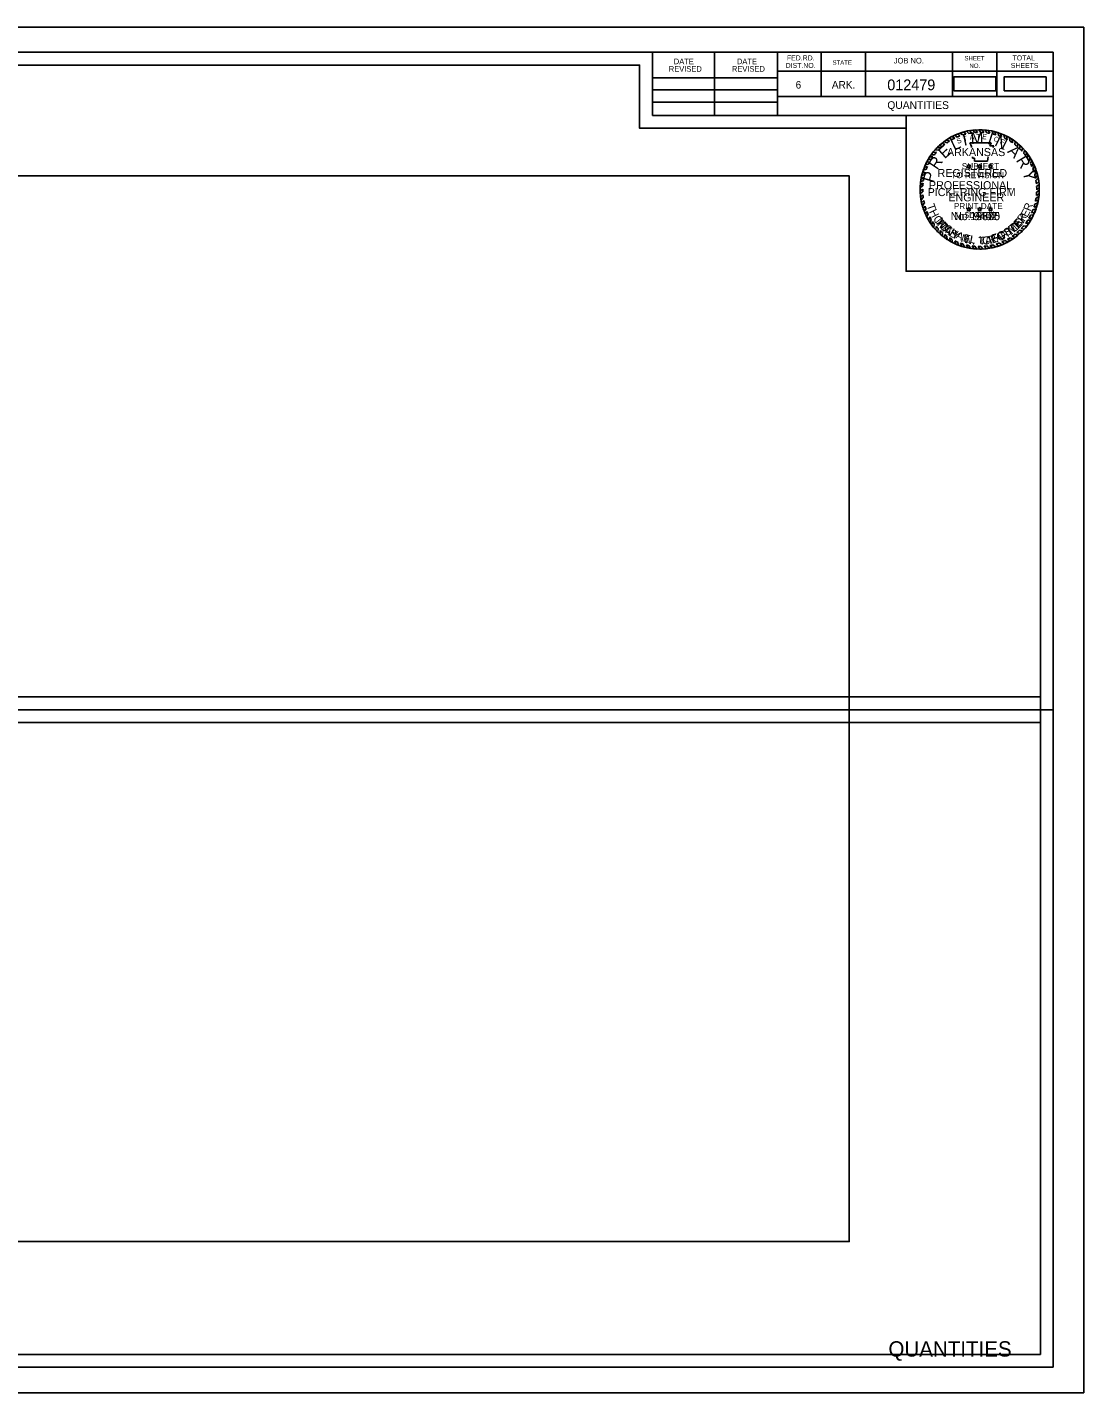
# Model space of a CAD drawing. Extents: x 1369290 to 1371547, y 379683 to 379897.
# Drawn here: x 1370188.9 to 1370354, y 379683.5 to 379896.8 of the extents above; entities that cross this region are included whole.
import ezdxf

# ---------------------------------------------------------------- set-up
doc = ezdxf.new("R2010")
doc.units = 0
for name, color, linetype in [('Default', 7, 'Continuous'), ('R_Border', 7, 'Continuous'), ('R_Border Notes', 7, 'Continuous'), ('R_Border Plan-Plan', 7, 'Continuous'), ('R_Border Title', 7, 'Continuous'), ('R_No Plot', 7, 'Continuous'), ('STAMP_PE_CRAFTON', 7, 'Continuous'), ('STAMP_PE_FOSTER', 7, 'Continuous'), ('STAMP_PE_SEAL-INFO', 7, 'Continuous'), ('STAMP_PE_TAEGTMEYER', 7, 'Continuous'), ('STAMP_PE_TXT', 7, 'Continuous'), ('STAMP_PRELIMINARY', 7, 'Continuous')]:
    doc.layers.add(name, color=color, linetype=linetype)

msp = doc.modelspace()

# ---------------------------------------------------------------- linework, layer by layer
at = {"layer": 'Default'}
for points in [[(1370333.72, 379886.89), (1370340.28, 379886.89), (1370340.28, 379889.08), (1370333.72, 379889.08)], [(1370341.59, 379886.89), (1370348.15, 379886.89), (1370348.15, 379889.08), (1370341.59, 379889.08)], [(1370057.32, 379707.1), (1370317.39, 379707.1), (1370317.39, 379873.59), (1370057.32, 379873.59)]]:
    msp.add_lwpolyline(points, close=True, dxfattribs=at)
at = {"layer": 'R_Border'}
for p, q in [((1370033.09, 379892.93), (1370349.27, 379892.93)), ((1370286.63, 379883.05), (1370286.63, 379892.93)), ((1370296.31, 379883.05), (1370296.31, 379892.93)), ((1370306.17, 379892.93), (1370306.17, 379883.05)), ((1370313.01, 379892.93), (1370313.01, 379885.99)), ((1370319.95, 379892.93), (1370319.95, 379885.99)), ((1370333.53, 379892.93), (1370333.53, 379885.99)), ((1370340.47, 379892.93), (1370340.47, 379885.99)), ((1370349.27, 379687.47), (1370349.27, 379892.93)), ((1370286.63, 379888.91), (1370306.17, 379888.91)), ((1370349.27, 379889.99), (1370306.17, 379889.99)), ((1370349.27, 379890.01), (1370349.27, 379890.01)), ((1370286.63, 379887.05), (1370306.17, 379887.05)), ((1370286.63, 379885.11), (1370306.17, 379885.11)), ((1370349.27, 379885.99), (1370306.17, 379885.99)), ((1370309.13, 379885.99), (1370349.27, 379885.99)), ((1370349.27, 379883.05), (1370286.63, 379883.05)), ((1370349.27, 379687.47), (1370033.09, 379687.47))]:
    msp.add_line(p, q, dxfattribs=at)
at = {"layer": 'R_Border Plan-Plan'}
msp.add_line((1370033.09, 379790.2), (1370349.27, 379790.2), dxfattribs=at)
at = {"layer": 'R_No Plot'}
for points in [[(1370020.68, 379896.82), (1370354.02, 379896.82), (1370354.02, 379683.48), (1370020.68, 379683.48)], [(1370347.27, 379792.2), (1370035.09, 379792.2), (1370035.09, 379890.93), (1370284.63, 379890.93), (1370284.63, 379881.05), (1370302.17, 379881.05), (1370326.27, 379881.05), (1370326.27, 379858.71), (1370347.27, 379858.71)], [(1370035.09, 379890.93), (1370284.63, 379890.93), (1370284.63, 379881.05), (1370302.17, 379881.05), (1370326.27, 379881.05), (1370326.27, 379858.71), (1370347.27, 379858.71), (1370347.27, 379689.47), (1370035.09, 379689.47)], [(1370326.27, 379883.05), (1370349.27, 379883.05), (1370349.27, 379858.71), (1370326.27, 379858.71)], [(1370035.09, 379788.2), (1370347.27, 379788.2), (1370347.27, 379689.47), (1370035.09, 379689.47)]]:
    msp.add_lwpolyline(points, close=True, dxfattribs=at)
at = {"layer": 'STAMP_PE_SEAL-INFO'}
for p, q in [((1370333.44, 379879.75), (1370333.91, 379879.52)), ((1370333.88, 379879.96), (1370334.26, 379879.68)), ((1370334.38, 379880.18), (1370334.68, 379879.85)), ((1370334.73, 379880.3), (1370335.11, 379880)), ((1370335.32, 379880.49), (1370335.61, 379880.14)), ((1370335.71, 379880.58), (1370336.07, 379880.24)), ((1370336.19, 379880.68), (1370336.49, 379880.31)), ((1370336.71, 379880.75), (1370336.99, 379880.37)), ((1370337.44, 379880.4), (1370337.13, 379880.79)), ((1370337.94, 379880.4), (1370337.66, 379880.81)), ((1370338.4, 379880.38), (1370338.14, 379880.81)), ((1370338.9, 379880.33), (1370338.61, 379880.77)), ((1370339.33, 379880.27), (1370339.07, 379880.72)), ((1370339.89, 379880.15), (1370339.72, 379880.61)), ((1370340.29, 379880.04), (1370340.13, 379880.51)), ((1370340.75, 379879.89), (1370340.6, 379880.37)), ((1370341.16, 379879.73), (1370341.02, 379880.23)), ((1370341.63, 379879.53), (1370341.52, 379880.02)), ((1370342.07, 379879.3), (1370341.98, 379879.81)), ((1370330.81, 379877.69), (1370331.33, 379877.65)), ((1370331.13, 379878.04), (1370331.68, 379877.99)), ((1370331.47, 379878.36), (1370331.93, 379878.22)), ((1370331.81, 379878.66), (1370332.34, 379878.56)), ((1370332.19, 379878.99), (1370332.64, 379878.78)), ((1370332.61, 379879.25), (1370333.05, 379879.05)), ((1370333, 379879.5), (1370333.43, 379879.27)), ((1370336.24, 379878.78), (1370339.59, 379878.78)), ((1370336.37, 379878.47), (1370336.24, 379878.78)), ((1370336.47, 379878.18), (1370336.37, 379878.47)), ((1370336.48, 379878.06), (1370336.47, 379878.18)), ((1370339.59, 379878.78), (1370339.36, 379878.29)), ((1370339.36, 379878.29), (1370340, 379878.29)), ((1370340, 379878.29), (1370339.85, 379878.06)), ((1370342.46, 379879.07), (1370342.42, 379879.57)), ((1370342.89, 379878.78), (1370342.86, 379879.3)), ((1370343.25, 379878.52), (1370343.29, 379879)), ((1370343.7, 379878.15), (1370343.72, 379878.67)), ((1370344.01, 379877.85), (1370344.08, 379878.35)), ((1370344.37, 379877.48), (1370344.44, 379878.01)), ((1370344.65, 379877.16), (1370344.78, 379877.63)), ((1370329.29, 379875.35), (1370329.79, 379875.46)), ((1370329.47, 379875.74), (1370329.97, 379875.81)), ((1370329.71, 379876.17), (1370330.19, 379876.19)), ((1370329.95, 379876.57), (1370330.47, 379876.6)), ((1370330.19, 379876.91), (1370330.69, 379876.91)), ((1370330.46, 379877.28), (1370331.01, 379877.3)), ((1370336.67, 379876.35), (1370336.64, 379876.57)), ((1370336.98, 379876.35), (1370336.67, 379876.35)), ((1370336.98, 379875.92), (1370336.98, 379876.35)), ((1370339.01, 379875.92), (1370336.98, 379875.92)), ((1370339.03, 379876.26), (1370339.01, 379875.92)), ((1370339.11, 379876.57), (1370339.03, 379876.26)), ((1370344.97, 379876.75), (1370345.1, 379877.25)), ((1370345.19, 379876.43), (1370345.37, 379876.89)), ((1370345.5, 379875.93), (1370345.68, 379876.42)), ((1370345.7, 379875.57), (1370345.92, 379876.01)), ((1370345.93, 379875.08), (1370346.15, 379875.57)), ((1370329.06, 379873.36), (1370328.59, 379873.11)), ((1370328.69, 379873.6), (1370329.16, 379873.8)), ((1370328.8, 379874.01), (1370329.27, 379874.18)), ((1370328.95, 379874.51), (1370329.44, 379874.65)), ((1370329.1, 379874.92), (1370329.61, 379875.07)), ((1370346.07, 379874.75), (1370346.33, 379875.18)), ((1370346.26, 379874.2), (1370346.53, 379874.67)), ((1370346.37, 379873.83), (1370346.66, 379874.28)), ((1370346.5, 379873.27), (1370346.82, 379873.72)), ((1370346.57, 379872.89), (1370346.93, 379873.25)), ((1370328.87, 379872.04), (1370328.45, 379871.78)), ((1370328.86, 379871.55), (1370328.45, 379871.21)), ((1370328.91, 379872.46), (1370328.47, 379872.18)), ((1370328.86, 379871.14), (1370328.47, 379870.81)), ((1370328.97, 379872.9), (1370328.52, 379872.68)), ((1370346.64, 379872.38), (1370347.01, 379872.72)), ((1370346.67, 379871.97), (1370347.06, 379872.26)), ((1370346.67, 379871.04), (1370347.09, 379871.32)), ((1370346.68, 379871.45), (1370347.09, 379871.77)), ((1370328.9, 379870.64), (1370328.53, 379870.29)), ((1370328.95, 379870.21), (1370328.6, 379869.84)), ((1370329.03, 379869.75), (1370328.69, 379869.39)), ((1370329.12, 379869.34), (1370328.81, 379868.92)), ((1370346.38, 379869.2), (1370346.86, 379869.4)), ((1370346.49, 379869.65), (1370346.95, 379869.84)), ((1370346.58, 379870.15), (1370347.03, 379870.37)), ((1370346.63, 379870.54), (1370347.07, 379870.79)), ((1370329.25, 379868.89), (1370328.95, 379868.47)), ((1370329.39, 379868.47), (1370329.1, 379868.05)), ((1370329.55, 379868.04), (1370329.29, 379867.62)), ((1370329.72, 379867.66), (1370329.5, 379867.19)), ((1370329.96, 379867.2), (1370329.77, 379866.71)), ((1370345.46, 379866.97), (1370345.96, 379867.03)), ((1370345.73, 379867.47), (1370346.22, 379867.54)), ((1370345.89, 379867.81), (1370346.38, 379867.9)), ((1370346.1, 379868.32), (1370346.59, 379868.45)), ((1370346.24, 379868.7), (1370346.73, 379868.9)), ((1370330.2, 379866.79), (1370330.01, 379866.32)), ((1370330.4, 379866.48), (1370330.29, 379865.93)), ((1370330.68, 379866.09), (1370330.58, 379865.56)), ((1370330.98, 379865.71), (1370330.9, 379865.19)), ((1370331.28, 379865.38), (1370331.22, 379864.85)), ((1370331.61, 379865.05), (1370331.58, 379864.52)), ((1370331.95, 379864.74), (1370331.95, 379864.21)), ((1370343.59, 379864.74), (1370344.06, 379864.61)), ((1370344, 379865.11), (1370344.44, 379864.97)), ((1370344.25, 379865.37), (1370344.73, 379865.29)), ((1370344.64, 379865.8), (1370345.1, 379865.73)), ((1370344.94, 379866.2), (1370345.45, 379866.2)), ((1370345.28, 379866.69), (1370345.76, 379866.69)), ((1370332.31, 379864.44), (1370332.33, 379863.92)), ((1370332.65, 379864.19), (1370332.69, 379863.68)), ((1370333.08, 379863.91), (1370333.14, 379863.4)), ((1370333.43, 379863.71), (1370333.52, 379863.19)), ((1370333.91, 379863.46), (1370334.06, 379862.94)), ((1370334.28, 379863.29), (1370334.45, 379862.78)), ((1370334.77, 379863.1), (1370334.98, 379862.59)), ((1370335.18, 379862.96), (1370335.41, 379862.47)), ((1370335.69, 379862.82), (1370335.9, 379862.36)), ((1370336.09, 379862.74), (1370336.34, 379862.28)), ((1370336.59, 379862.66), (1370336.83, 379862.21)), ((1370337.03, 379862.61), (1370337.3, 379862.18)), ((1370337.51, 379862.58), (1370337.81, 379862.17)), ((1370337.97, 379862.58), (1370338.31, 379862.18)), ((1370338.49, 379862.61), (1370338.81, 379862.23)), ((1370338.93, 379862.65), (1370339.3, 379862.29)), ((1370339.37, 379862.72), (1370339.76, 379862.38)), ((1370339.86, 379862.83), (1370340.24, 379862.5)), ((1370340.32, 379862.95), (1370340.74, 379862.65)), ((1370340.82, 379863.11), (1370341.26, 379862.84)), ((1370341.24, 379863.28), (1370341.66, 379863.02)), ((1370341.7, 379863.49), (1370342.18, 379863.28)), ((1370342.1, 379863.7), (1370342.52, 379863.47)), ((1370342.52, 379863.95), (1370342.97, 379863.75)), ((1370342.86, 379864.17), (1370343.3, 379863.98)), ((1370343.32, 379864.52), (1370343.79, 379864.37))]:
    msp.add_line(p, q, dxfattribs=at)
for radius, start, end in [(9.32, 117.6544, 120.8099), (9.32, 111.3124, 114.7026), (8.91, 110.3086, 113.1659), (9.32, 105.2339, 109.0352), (8.91, 104.0352, 107.3615), (9.32, 99.7525, 102.7765), (8.91, 98.258, 101.0329), (9.32, 93.9381, 96.5517), (8.91, 92.1102, 95.0367), (9.32, 87.7298, 90.6707), (8.91, 85.9628, 88.9097), (9.32, 81.9732, 84.8236), (8.91, 79.9264, 82.696), (9.32, 75.3125, 77.9426), (8.91, 73.5575, 76.2314), (9.32, 69.6061, 72.3058), (8.91, 67.6248, 70.504), (9.32, 63.1329, 66.2704), (9.32, 135.4021, 138.3031), (8.91, 133.1331, 136.2562), (9.32, 129.7326, 132.5376), (8.91, 127.5297, 130.9683), (9.32, 123.6199, 126.5906), (8.91, 121.9746, 125.11), (8.91, 115.6869, 119.1583), (8.91, 61.1558, 64.3784), (9.32, 56.9003, 60.0942), (8.91, 54.9238, 58.2702), (8.91, 48.3016, 52.0395), (9.32, 50.3492, 53.7159), (8.91, 42.2212, 45.5512), (9.32, 44.3405, 47.3929), (9.32, 38.1247, 41.2316), (9.32, 152.864, 155.5189), (9.32, 147.0072, 149.899), (8.91, 151.0315, 153.573), (9.32, 141.6056, 144.4486), (8.91, 145.0197, 148.2104), (8.91, 139.301, 142.5873), (8.91, 36.135, 39.5311), (8.91, 29.9032, 33.6645), (9.32, 31.9614, 35.4294), (8.91, 23.7732, 27.2211), (9.32, 25.9391, 29.0125), (9.32, 164.3068, 166.894), (9.32, 158.4077, 161.0701), (8.91, 167.9048, 170.9039), (8.91, 162.4331, 165.0013), (8.91, 156.3402, 159.2319), (8.91, 17.6802, 21.4251), (9.32, 19.9538, 23.3141), (8.91, 11.5444, 15.2364), (9.32, 13.8421, 17.4447), (9.32, 7.5852, 10.8621), (9.32, 175.7409, 178.2066), (9.32, 181.7251, 184.1626), (9.32, 170.0003, 172.6878), (8.91, 179.6454, 182.2633), (8.91, 173.73, 176.4734), (8.91, 5.7599, 9.0606), (8.91, 359.7329, 3.0639), (9.32, 1.7215, 4.7268), (9.32, 355.7156, 358.9569), (9.32, 187.4204, 190.1927), (9.32, 193.0369, 195.9973), (8.91, 185.4539, 188.234), (8.91, 191.2274, 193.9858), (8.91, 341.777, 345.0925), (8.91, 348.0778, 351.3435), (8.91, 353.8632, 357.1274), (9.32, 343.8925, 347.035), (9.32, 349.8305, 353.0885), (9.32, 198.8967, 201.6281), (8.91, 196.9675, 199.8353), (9.32, 204.5479, 207.4328), (8.91, 202.7761, 205.4791), (8.91, 208.7883, 211.7934), (8.91, 329.5549, 333.2076), (8.91, 335.6038, 339.1858), (9.32, 331.4037, 334.9332), (9.32, 337.3837, 340.9933), (9.32, 210.8636, 213.6571), (9.32, 216.6115, 219.491), (8.91, 214.1838, 217.2747), (9.32, 222.48, 225.3801), (8.91, 220.3909, 223.3056), (8.91, 226.2494, 229.2407), (8.91, 310.7744, 314.3161), (9.32, 312.4518, 315.6633), (8.91, 316.6531, 320.3711), (9.32, 318.2846, 321.8043), (8.91, 323.5851, 327.4407), (9.32, 325.4405, 328.9872), (9.32, 228.3665, 231.348), (8.91, 232.229, 234.9336), (9.32, 234.295, 236.9452), (8.91, 238.2223, 240.8353), (9.32, 240.1977, 242.8613), (8.91, 244.3204, 246.9486), (9.32, 246.576, 249.1558), (8.91, 250.3491, 253.1216), (9.32, 252.5967, 255.3252), (8.91, 256.505, 259.1192), (8.91, 262.3783, 265.2012), (8.91, 268.3215, 271.277), (8.91, 274.6157, 277.4486), (8.91, 280.3459, 283.5814), (8.91, 286.6423, 289.9783), (9.32, 288.5709, 291.9733), (8.91, 292.8745, 296.1185), (9.32, 294.6481, 298.2166), (8.91, 299.0768, 302.1724), (9.32, 300.621, 303.8703), (8.91, 304.823, 308.5143), (9.32, 306.3721, 310.208), (9.32, 258.4433, 261.1398), (9.32, 264.1978, 267.1009), (9.32, 270.2548, 273.3361), (9.32, 276.4239, 279.4357), (9.32, 282.3199, 285.3702)]:
    msp.add_arc((1370337.77, 379871.49), radius, start, end, dxfattribs=at)
at = {"layer": 'STAMP_PE_TXT'}
for p, q in [((1370336, 379875.21), (1370336.07, 379875.44)), ((1370336.07, 379875.44), (1370336.15, 379875.21)), ((1370337.7, 379875.21), (1370337.77, 379875.44)), ((1370337.77, 379875.44), (1370337.85, 379875.21)), ((1370339.39, 379875.21), (1370339.47, 379875.44)), ((1370339.47, 379875.44), (1370339.54, 379875.21)), ((1370335.95, 379875.06), (1370335.75, 379875.21)), ((1370335.75, 379875.21), (1370336, 379875.21)), ((1370335.87, 379874.83), (1370335.95, 379875.06)), ((1370336.07, 379874.97), (1370335.87, 379874.83)), ((1370336.27, 379874.83), (1370336.07, 379874.97)), ((1370336.15, 379875.21), (1370336.39, 379875.21)), ((1370336.39, 379875.21), (1370336.2, 379875.06)), ((1370336.2, 379875.06), (1370336.27, 379874.83)), ((1370337.65, 379875.06), (1370337.45, 379875.21)), ((1370337.45, 379875.21), (1370337.7, 379875.21)), ((1370337.57, 379874.83), (1370337.65, 379875.06)), ((1370337.77, 379874.97), (1370337.57, 379874.83)), ((1370337.97, 379874.83), (1370337.77, 379874.97)), ((1370337.85, 379875.21), (1370338.09, 379875.21)), ((1370338.09, 379875.21), (1370337.89, 379875.06)), ((1370337.89, 379875.06), (1370337.97, 379874.83)), ((1370339.35, 379875.06), (1370339.15, 379875.21)), ((1370339.15, 379875.21), (1370339.39, 379875.21)), ((1370339.27, 379874.83), (1370339.35, 379875.06)), ((1370339.47, 379874.97), (1370339.27, 379874.83)), ((1370339.67, 379874.83), (1370339.47, 379874.97)), ((1370339.54, 379875.21), (1370339.79, 379875.21)), ((1370339.79, 379875.21), (1370339.59, 379875.06)), ((1370339.59, 379875.06), (1370339.67, 379874.83)), ((1370335.95, 379868.35), (1370335.75, 379868.5)), ((1370335.75, 379868.5), (1370336, 379868.5)), ((1370335.87, 379868.12), (1370335.95, 379868.35)), ((1370336.07, 379868.27), (1370335.87, 379868.12)), ((1370336, 379868.5), (1370336.07, 379868.73)), ((1370336.07, 379868.73), (1370336.15, 379868.5)), ((1370336.27, 379868.12), (1370336.07, 379868.27)), ((1370336.15, 379868.5), (1370336.39, 379868.5)), ((1370336.39, 379868.5), (1370336.2, 379868.35)), ((1370336.2, 379868.35), (1370336.27, 379868.12)), ((1370337.65, 379868.35), (1370337.45, 379868.5)), ((1370337.45, 379868.5), (1370337.7, 379868.5)), ((1370337.57, 379868.12), (1370337.65, 379868.35)), ((1370337.77, 379868.27), (1370337.57, 379868.12)), ((1370337.7, 379868.5), (1370337.77, 379868.73)), ((1370337.77, 379868.73), (1370337.85, 379868.5)), ((1370337.97, 379868.12), (1370337.77, 379868.27)), ((1370337.85, 379868.5), (1370338.09, 379868.5)), ((1370338.09, 379868.5), (1370337.89, 379868.35)), ((1370337.89, 379868.35), (1370337.97, 379868.12)), ((1370339.35, 379868.35), (1370339.15, 379868.5)), ((1370339.15, 379868.5), (1370339.39, 379868.5)), ((1370339.27, 379868.12), (1370339.35, 379868.35)), ((1370339.47, 379868.27), (1370339.27, 379868.12)), ((1370339.39, 379868.5), (1370339.47, 379868.73)), ((1370339.47, 379868.73), (1370339.54, 379868.5)), ((1370339.67, 379868.12), (1370339.47, 379868.27)), ((1370339.54, 379868.5), (1370339.79, 379868.5)), ((1370339.79, 379868.5), (1370339.59, 379868.35)), ((1370339.59, 379868.35), (1370339.67, 379868.12))]:
    msp.add_line(p, q, dxfattribs=at)
at = {"layer": 'STAMP_PRELIMINARY'}
msp.add_circle((1370337.77, 379871.49), 9.32, dxfattribs=at)

# ---------------------------------------------------------------- texts
at = {"layer": 'R_Border'}
for s, height, p in [('FED.RD.', 0.782, (1370307.65, 379891.65)), ('TOTAL', 0.782, (1370342.91, 379891.65)), ('REVISED', 0.879, (1370289.19, 379889.88)), ('DATE', 0.879, (1370289.97, 379891.06)), ('REVISED', 0.879, (1370299.05, 379889.88)), ('DATE', 0.879, (1370299.83, 379891.06)), ('DIST.NO.', 0.782, (1370307.45, 379890.47)), ('STATE', 0.684, (1370314.77, 379890.97)), ('JOB NO.', 0.879, (1370324.35, 379891.17)), ('SHEET', 0.684, (1370335.39, 379891.65)), ('NO.', 0.684, (1370336.17, 379890.47)), ('SHEETS', 0.782, (1370342.63, 379890.47)), ('6', 1.17, (1370309.01, 379887.25)), ('ARK.', 1.172, (1370314.67, 379887.25))]:
    msp.add_text(s, height=height, dxfattribs=at).set_placement(p)
at = {"layer": 'R_Border Notes'}
for s, height, p in [('012479', 1.68, (1370323.33, 379886.99)), ('QUANTITIES', 1.2, (1370323.34, 379884.07))]:
    msp.add_text(s, height=height, dxfattribs=at).set_placement(p)
at = {"layer": 'R_Border Title'}
msp.add_text('QUANTITIES', height=2.4, dxfattribs=at).set_placement((1370323.51, 379689.12))
at = {"layer": 'STAMP_PE_CRAFTON'}
for s, rotation, p in [('T', 310.7442, (1370330.74, 379866.39)), ('N', 49.2411, (1370344.05, 379865.51)), ('O', 317.6422, (1370331.4, 379865.58)), ('N', 324.4537, (1370332.25, 379864.79)), ('Y', 331.1686, (1370333.28, 379864.08)), ('F', 28.7821, (1370341.43, 379863.62)), ('T', 34.1136, (1370342.35, 379864.13)), ('O', 41.8391, (1370343.21, 379864.73)), ('N', 347.4752, (1370335.34, 379863.16)), ('.', 356.8926, (1370336.57, 379862.88)), ('C', 6.0117, (1370338.24, 379862.83)), ('R', 14.8189, (1370339.34, 379862.95)), ('A', 20.5125, (1370340.45, 379863.25))]:
    msp.add_text(s, height=1.25, rotation=rotation, dxfattribs=at).set_placement(p)
msp.add_text('No. 12370', height=1.25, dxfattribs=at).set_placement((1370333.23, 379866.69))
at = {"layer": 'STAMP_PE_FOSTER'}
for s, rotation, p in [('M', 308.339, (1370330.89, 379866.51)), ('E', 46.9613, (1370343.77, 379865.48)), ('R', 54.5031, (1370344.5, 379866.3)), ('I', 314.1842, (1370331.68, 379865.57)), ('C', 319.8733, (1370332.04, 379865.22)), ('H', 327.7235, (1370332.97, 379864.48)), ('A', 335.7276, (1370333.95, 379863.9)), ('O', 23.719, (1370340.85, 379863.57)), ('S', 31.7234, (1370341.96, 379864.1)), ('T', 39.4194, (1370342.91, 379864.73)), ('E', 343.5779, (1370335.09, 379863.43)), ('L', 350.8115, (1370336.14, 379863.16)), ('L', 1.2666, (1370337.68, 379863)), ('.', 6.8035, (1370338.73, 379863.06)), ('F', 15.8691, (1370339.81, 379863.24))]:
    msp.add_text(s, height=1.2, rotation=rotation, dxfattribs=at).set_placement(p)
msp.add_text('No. 9402', height=1.25, dxfattribs=at).set_placement((1370333.76, 379866.69))
at = {"layer": 'STAMP_PE_TAEGTMEYER'}
for s, rotation, p in [('T', 289.646, (1370329.47, 379869)), ('R', 69.57, (1370345.72, 379868)), ('H', 296.7339, (1370329.83, 379868.02)), ('O', 303.7708, (1370330.42, 379866.91)), ('E', 46.8094, (1370343.81, 379865.27)), ('Y', 53.9986, (1370344.55, 379866.08)), ('E', 63.0984, (1370345.22, 379867.02)), ('M', 314.2033, (1370331.07, 379865.96)), ('A', 321.0594, (1370332.03, 379864.99)), ('S', 327.8239, (1370332.86, 379864.35)), ('G', 23.3052, (1370340.77, 379863.35)), ('T', 31.466, (1370341.87, 379863.84)), ('M', 39.3, (1370342.77, 379864.39)), ('N', 344.2727, (1370334.76, 379863.34)), ('.', 350.6464, (1370335.97, 379863.01)), ('T', 3.0061, (1370337.64, 379862.81)), ('A', 8.9826, (1370338.68, 379862.87)), ('E', 17.6836, (1370339.72, 379863.02))]:
    msp.add_text(s, height=1.25, rotation=rotation, dxfattribs=at).set_placement(p)
msp.add_text('No. 19605', height=1.25, dxfattribs=at).set_placement((1370333.23, 379866.69))
at = {"layer": 'STAMP_PE_TXT'}
for s, rotation, p in [('T', 16.311, (1370335.29, 379878.97)), ('A', 9.0679, (1370336.26, 379879.22)), ('T', 1.8248, (1370337.24, 379879.35)), ('E', 355.2002, (1370338.15, 379879.36)), ('O', 342.2506, (1370339.88, 379879.08)), ('S', 23.5541, (1370334.37, 379878.59)), ('F', 335.0075, (1370340.84, 379878.74))]:
    msp.add_text(s, height=0.781, rotation=rotation, dxfattribs=at).set_placement(p)
for s, p in [('ARKANSAS', (1370332.66, 379876.7)), ('REGISTERED', (1370331.19, 379873.43)), ('PROFESSIONAL', (1370329.84, 379871.53)), ('ENGINEER', (1370332.88, 379869.63))]:
    msp.add_text(s, height=1.25, dxfattribs=at).set_placement(p)
at = {"layer": 'STAMP_PRELIMINARY'}
for s, rotation, p in [('I', 12.5248, (1370335.31, 379878.28)), ('M', 3.1074, (1370336.41, 379878.59)), ('I', 342.3164, (1370338.87, 379878.65)), ('N', 333.9382, (1370339.98, 379878.38)), ('E', 42.3578, (1370332.3, 379876.19)), ('L', 25.513, (1370333.78, 379877.52)), ('A', 315.6579, (1370342.02, 379877.35)), ('R', 56.2292, (1370331.14, 379874.45)), ('R', 301.3831, (1370343.38, 379876.04)), ('P', 73.913, (1370330.59, 379872.43)), ('Y', 283.2593, (1370344.47, 379874.25))]:
    msp.add_text(s, height=1.8, rotation=rotation, dxfattribs=at).set_placement(p)
for s, height, p in [('SUBJECT', 0.96, (1370334.97, 379874.64)), ('TO REVISION', 0.96, (1370333.31, 379873.25)), ('PICKERING FIRM', 1.25, (1370329.64, 379870.45)), ('PRINT DATE', 0.96, (1370333.73, 379868.41)), ('$DATE$', 0.96, (1370335.41, 379867.02))]:
    msp.add_text(s, height=height, dxfattribs=at).set_placement(p)

doc.saveas('drawing.dxf')
